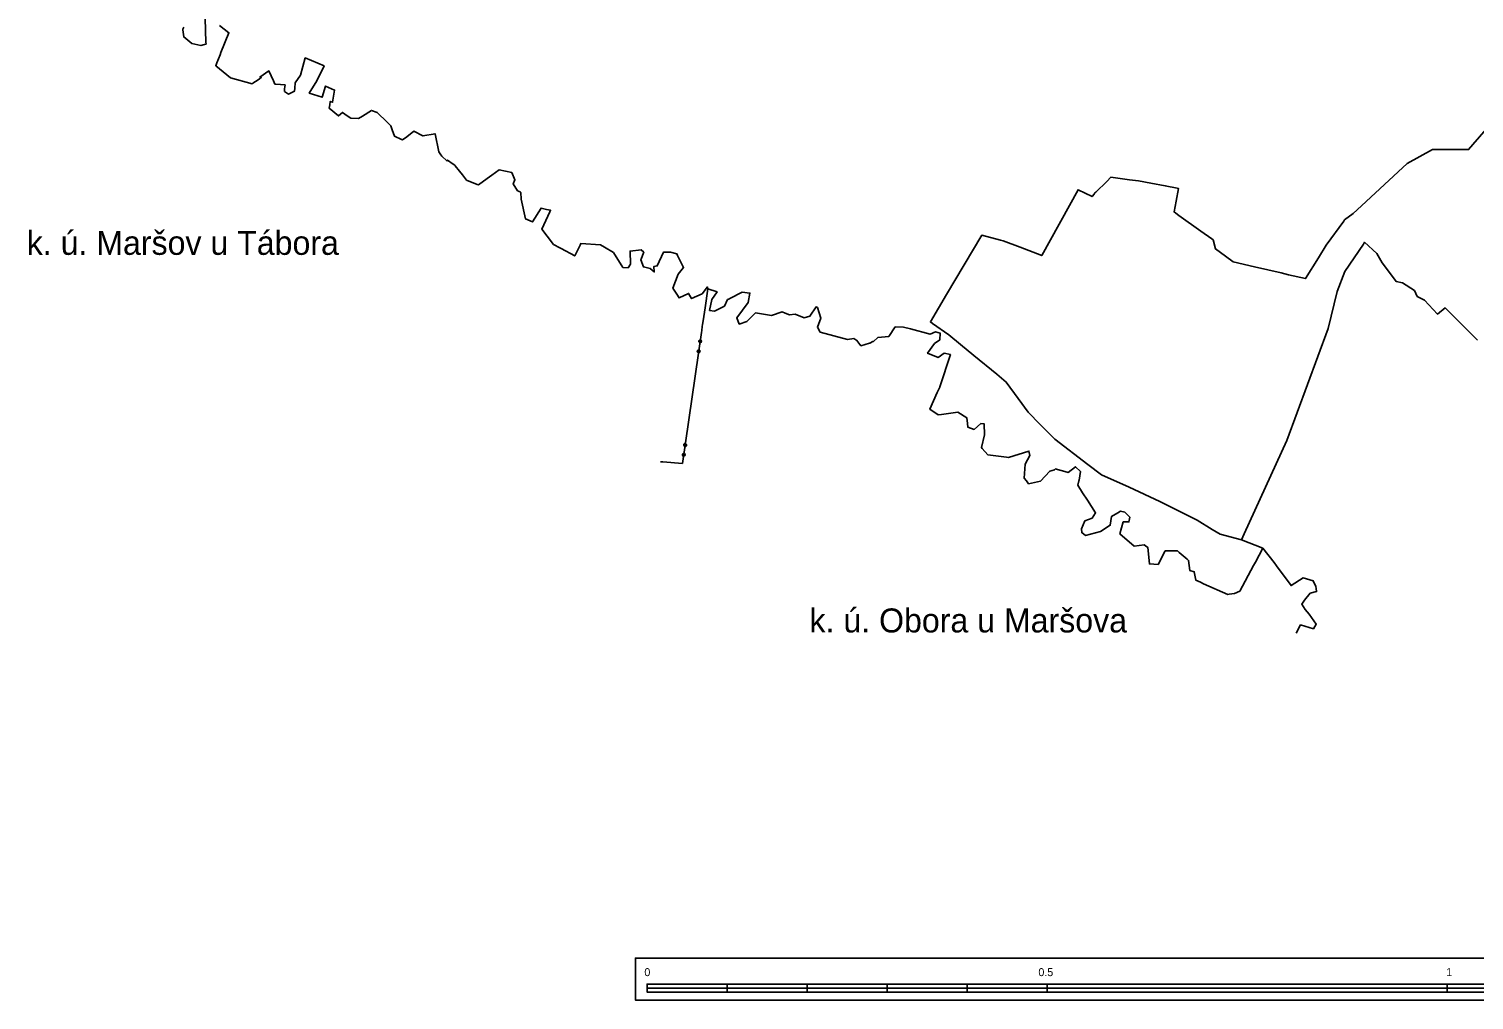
# Model space of a CAD drawing. Extents: x -738273 to -735126, y -1127782 to -1123636.
# Drawn here: x -738273 to -736466, y -1127782 to -1126567 of the extents above; entities that cross this region are included whole.
import ezdxf

# ---------------------------------------------------------------- set-up
doc = ezdxf.new("R2010")
doc.units = 0
for name, color, linetype in [('GR_MER', 7, 'Continuous'), ('HRA_KU', 7, 'Continuous'), ('KU_OST', 7, 'Continuous'), ('NERES_SET', 7, 'Continuous'), ('OVNE_PRE', 7, 'Continuous'), ('OVNE_SET', 7, 'Continuous')]:
    doc.layers.add(name, color=color, linetype=linetype)

msp = doc.modelspace()

# ---------------------------------------------------------------- linework, layer by layer
at = {"layer": 'GR_MER'}
for points in [[(-735903.2, -1127729.5), (-735903.2, -1127782), (-737514.6, -1127782), (-737514.6, -1127729.5), (-735903.2, -1127729.5)], [(-737500.1, -1127767), (-737500.1, -1127762), (-737400.1, -1127762)], [(-737300.1, -1127772), (-737400.1, -1127772), (-737400.1, -1127767)], [(-737300.1, -1127767), (-737300.1, -1127762), (-737200.1, -1127762)], [(-737100.1, -1127772), (-737200.1, -1127772), (-737200.1, -1127767)], [(-737100.1, -1127767), (-737100.1, -1127762), (-737000.1, -1127762)], [(-736500.1, -1127772), (-737000.1, -1127772), (-737000.1, -1127767)], [(-736500.1, -1127767), (-736500.1, -1127762), (-736000.1, -1127762)]]:
    msp.add_lwpolyline(points, dxfattribs=at)
for points in [[(-737400.1, -1127772), (-737500.1, -1127772), (-737500.1, -1127767), (-737400.1, -1127767)], [(-737300.1, -1127767), (-737400.1, -1127767), (-737400.1, -1127762), (-737300.1, -1127762)], [(-737200.1, -1127772), (-737300.1, -1127772), (-737300.1, -1127767), (-737200.1, -1127767)], [(-737100.1, -1127767), (-737200.1, -1127767), (-737200.1, -1127762), (-737100.1, -1127762)], [(-737000.1, -1127772), (-737100.1, -1127772), (-737100.1, -1127767), (-737000.1, -1127767)], [(-736500.1, -1127767), (-737000.1, -1127767), (-737000.1, -1127762), (-736500.1, -1127762)], [(-736000.1, -1127772), (-736500.1, -1127772), (-736500.1, -1127767), (-736000.1, -1127767)]]:
    msp.add_lwpolyline(points, close=True, dxfattribs=at)
at = {"layer": 'HRA_KU'}
for points in [[(-737424.2, -1126892.4), (-737427.6, -1126916.3), (-737429.9, -1126932.4), (-737430.6, -1126937.3), (-737431, -1126939.7), (-737431.7, -1126944.7), (-737432, -1126946.9), (-737455.8, -1127111.1)], [(-737432.2, -1126959.2), (-737433.3, -1126960), (-737434.6, -1126959.8), (-737435.4, -1126958.7), (-737435.2, -1126957.4), (-737434.1, -1126956.6), (-737432.8, -1126956.8), (-737432, -1126957.9), (-737432.2, -1126959.2), (-737432.4, -1126959.1), (-737432.2, -1126957.9), (-737432.5, -1126957.5), (-737432.8, -1126959.5), (-737433.3, -1126959.8), (-737432.9, -1126957), (-737433.3, -1126957), (-737433.7, -1126959.7), (-737434.1, -1126959.7), (-737433.7, -1126956.9), (-737434.1, -1126956.9), (-737434.5, -1126959.6), (-737434.8, -1126959.2), (-737434.5, -1126957.2), (-737435, -1126957.5), (-737435.1, -1126958.7)], [(-737434, -1126971.6), (-737435, -1126972.4), (-737436.4, -1126972.2), (-737437.2, -1126971.1), (-737437, -1126969.8), (-737435.9, -1126969), (-737434.6, -1126969.2), (-737433.8, -1126970.2), (-737434, -1126971.6), (-737434.1, -1126971.4), (-737434, -1126970.2), (-737434.3, -1126969.7), (-737434.6, -1126971.7), (-737435.1, -1126972.1), (-737434.7, -1126969.3), (-737435, -1126969.2), (-737435.4, -1126972), (-737435.8, -1126972), (-737435.4, -1126969.2), (-737435.8, -1126969.1), (-737436.2, -1126971.9), (-737436.6, -1126971.4), (-737436.3, -1126969.5), (-737436.7, -1126969.8), (-737436.9, -1126971)], [(-737450.9, -1127088.7), (-737452, -1127089.5), (-737453.3, -1127089.3), (-737454.1, -1127088.2), (-737453.9, -1127086.9), (-737452.8, -1127086.1), (-737451.5, -1127086.3), (-737450.7, -1127087.3), (-737450.9, -1127088.7), (-737451.1, -1127088.6), (-737450.9, -1127087.4), (-737451.3, -1127087), (-737451.5, -1127088.9), (-737452, -1127089.3), (-737451.6, -1127086.5), (-737452, -1127086.5), (-737452.4, -1127089.2), (-737452.8, -1127089.2), (-737452.4, -1127086.4), (-737452.8, -1127086.3), (-737453.2, -1127089.1), (-737453.5, -1127088.7), (-737453.2, -1127086.7), (-737453.7, -1127087), (-737453.9, -1127088.2)], [(-737452.7, -1127101.1), (-737453.8, -1127101.9), (-737455.1, -1127101.7), (-737455.9, -1127100.6), (-737455.7, -1127099.3), (-737454.6, -1127098.5), (-737453.3, -1127098.6), (-737452.5, -1127099.7), (-737452.7, -1127101.1), (-737452.9, -1127100.9), (-737452.7, -1127099.7), (-737453, -1127099.2), (-737453.3, -1127101.2), (-737453.8, -1127101.6), (-737453.4, -1127098.8), (-737453.8, -1127098.7), (-737454.2, -1127101.5), (-737454.6, -1127101.4), (-737454.2, -1127098.7), (-737454.6, -1127098.6), (-737455, -1127101.4), (-737455.3, -1127100.9), (-737455, -1127099), (-737455.5, -1127099.3), (-737455.6, -1127100.5)], [(-737455.8, -1127111.1), (-737480.4, -1127109), (-737483.4, -1127108.7)], [(-736730.2, -1127216.8), (-736716.4, -1127234.7), (-736713.2, -1127239.1), (-736695.1, -1127263.6), (-736680, -1127253.9), (-736667.4, -1127257.5), (-736664.1, -1127264.6), (-736663.8, -1127267.1), (-736663.2, -1127271), (-736671.2, -1127273.2), (-736678.2, -1127281.8), (-736681.8, -1127287), (-736677.5, -1127293.6), (-736672.4, -1127299.2), (-736663.7, -1127311.7), (-736667.2, -1127317.5), (-736683.2, -1127312.8), (-736688.8, -1127323)]]:
    msp.add_lwpolyline(points, dxfattribs=at)
at = {"layer": 'NERES_SET'}
for points in [[(-736440.3, -1126680.2), (-736473.1, -1126718.4), (-736481.2, -1126718.4), (-736511.7, -1126718.2), (-736518.2, -1126718.1), (-736550.1, -1126735.6), (-736612.3, -1126793.6), (-736617.4, -1126798.3), (-736628.3, -1126806.4), (-736629.2, -1126807.7), (-736651.2, -1126838), (-736660.8, -1126853.6), (-736677, -1126879.7), (-736698.3, -1126874.8), (-736707.4, -1126872.7), (-736740.8, -1126864.9), (-736767.5, -1126858.7), (-736777, -1126851.8), (-736789.5, -1126842.5), (-736792.3, -1126831.4), (-736794.2, -1126830.1), (-736807.7, -1126820.4), (-736835.2, -1126800.7), (-736839.2, -1126797.9), (-736841.3, -1126796.4), (-736838.8, -1126782.8), (-736835.9, -1126766.9), (-736837.3, -1126766.6)], [(-736837.3, -1126766.6), (-736852.3, -1126763.5), (-736870.5, -1126760.3), (-736885.9, -1126757.6), (-736897.1, -1126756), (-736920.2, -1126752.9), (-736925.4, -1126758.1), (-736939.3, -1126771.7), (-736940.2, -1126772.6), (-736941.3, -1126774.1), (-736943.7, -1126777.1), (-736961.2, -1126768.6), (-737006.7, -1126851), (-737033.7, -1126840.6), (-737054.9, -1126832.5), (-737058.2, -1126831.6), (-737081.6, -1126825.4), (-737125.6, -1126899.7), (-737145.9, -1126933.9), (-737143.3, -1126935.8), (-737122.8, -1126950.2), (-737108.2, -1126962.1), (-737091.6, -1126975.8), (-737062.9, -1126999.4), (-737051.1, -1127009.2), (-737036.2, -1127029.7), (-737023.8, -1127046.8), (-737008.5, -1127062.2), (-736990.2, -1127080.6), (-736949, -1127112.2), (-736932.1, -1127125.3), (-736897.5, -1127140.6), (-736859, -1127158.3), (-736812.5, -1127181.9), (-736793.5, -1127193.5), (-736783.9, -1127199.4), (-736757.2, -1127206.4)]]:
    msp.add_lwpolyline(points, dxfattribs=at)
at = {"layer": 'OVNE_PRE'}
for points in [[(-738078.9, -1126565.2), (-738080.3, -1126567.7), (-738080.2, -1126568.6), (-738079.2, -1126577.5), (-738068.9, -1126585.6), (-738057.7, -1126588.3), (-738053.1, -1126586.9), (-738051.3, -1126586.4), (-738051.4, -1126584), (-738052.3, -1126554.4)], [(-738034.6, -1126563.3), (-738022.7, -1126572.2), (-738032.6, -1126596.8), (-738033.8, -1126599.9), (-738037.8, -1126610), (-738039.2, -1126613.5), (-738020.7, -1126628.5), (-737993.8, -1126636.2), (-737992.6, -1126635.4), (-737986.3, -1126631.1), (-737982.2, -1126628.3), (-737983.9, -1126627.7), (-737972.7, -1126619.9), (-737966.9, -1126632.5), (-737965.1, -1126636.5), (-737964, -1126636.7), (-737952.5, -1126637.4), (-737953, -1126642.6), (-737953.1, -1126645.6), (-737948.4, -1126649.1), (-737942.5, -1126646.3), (-737940.8, -1126645.5), (-737940.4, -1126641.5), (-737939.9, -1126635.1), (-737933.1, -1126625.4), (-737927.2, -1126603.7), (-737903.7, -1126613.7), (-737912.8, -1126632.5), (-737922.3, -1126647.7), (-737906.3, -1126653), (-737902, -1126639), (-737890.7, -1126643.9), (-737893.1, -1126659.2), (-737896.1, -1126658.2), (-737896.7, -1126662.4), (-737897.3, -1126666.6), (-737885.6, -1126676.2), (-737880.9, -1126671.9), (-737875, -1126676), (-737870.5, -1126679.2), (-737860.8, -1126679.7), (-737855.8, -1126676.5), (-737844.5, -1126669.4), (-737837.5, -1126672), (-737825, -1126684.1), (-737820.4, -1126688.6), (-737818.5, -1126693.8), (-737815.8, -1126701.4), (-737806.8, -1126705.8), (-737805.7, -1126706.3), (-737800.4, -1126702.3), (-737791.5, -1126695.5), (-737780.1, -1126701.3), (-737764.9, -1126698.6), (-737760.2, -1126721), (-737757.7, -1126724.8), (-737756.7, -1126726.4), (-737750.3, -1126732.6), (-737749.4, -1126731.5), (-737742.3, -1126736.5), (-737740.3, -1126737.9), (-737739.8, -1126738.6), (-737734.5, -1126745.3), (-737730.7, -1126750.1), (-737725.6, -1126756.6), (-737712.2, -1126761.9), (-737710.9, -1126762.4), (-737700, -1126754.5), (-737694.1, -1126750.3), (-737684.9, -1126743.6), (-737669.2, -1126747.1), (-737665.1, -1126756.1), (-737667.5, -1126761.3), (-737661.8, -1126769.9), (-737658.5, -1126771.1), (-737657.9, -1126772), (-737657.3, -1126780.2), (-737652, -1126804.9), (-737643.2, -1126808.9), (-737632.6, -1126791.5), (-737630.8, -1126791.9), (-737625.8, -1126793.1), (-737620.7, -1126794.3), (-737621.5, -1126796.1), (-737631.7, -1126817.9), (-737624.9, -1126826.6), (-737616.8, -1126837), (-737608.9, -1126841.3), (-737607.2, -1126842.2), (-737590.4, -1126851.3), (-737583.8, -1126837.8), (-737582.9, -1126835.9), (-737558.1, -1126837.4), (-737553.4, -1126840.2), (-737542, -1126847.1), (-737530.3, -1126865.8), (-737523.8, -1126866.1), (-737520.6, -1126861.7), (-737521.3, -1126845.3), (-737507.4, -1126843.6), (-737504.1, -1126846.7), (-737507.8, -1126856.3), (-737504.5, -1126865.1), (-737496.3, -1126867), (-737491.1, -1126871.3), (-737491.4, -1126864.5), (-737487.4, -1126863.9), (-737479.6, -1126846.8), (-737470.6, -1126846.6), (-737462.8, -1126848.9), (-737461.8, -1126850.9), (-737454.3, -1126865.8), (-737461.1, -1126874.3), (-737467.8, -1126891.5), (-737462.9, -1126899.2), (-737460, -1126903.8), (-737448.2, -1126898.2), (-737444.3, -1126904.6), (-737431.2, -1126898.7), (-737424.5, -1126890.1), (-737424.2, -1126892.4)], [(-737424.2, -1126892.4), (-737412.5, -1126896.3), (-737419.2, -1126905.8), (-737421.9, -1126919.5), (-737415.8, -1126920.4), (-737415, -1126920), (-737403.1, -1126914), (-737399.3, -1126905.9), (-737397.1, -1126904.8), (-737396.5, -1126904.5), (-737381.3, -1126896.8), (-737371.5, -1126897.8), (-737373.6, -1126909.7), (-737388, -1126928.9), (-737384.9, -1126936.6), (-737375.5, -1126933.2), (-737364.3, -1126922.5), (-737344.6, -1126925.7), (-737331.2, -1126921.4), (-737327.5, -1126922.8), (-737321.9, -1126924.9), (-737315.1, -1126924.1), (-737303.7, -1126928.9), (-737296.4, -1126926.6), (-737288.8, -1126915.2), (-737287.2, -1126915.9), (-737283, -1126929), (-737287.1, -1126940.6), (-737283.6, -1126946.5), (-737249.5, -1126955.8), (-737241.7, -1126954.7), (-737237.7, -1126957.1), (-737236.4, -1126958.7), (-737232.7, -1126963.6), (-737222.1, -1126960.6), (-737221.7, -1126960.4), (-737217.7, -1126958.5), (-737216.9, -1126958.2), (-737211.4, -1126953.3), (-737198, -1126952), (-737189.8, -1126940.2), (-737179.7, -1126940.3), (-737170.7, -1126942.7), (-737146.3, -1126949.2), (-737139.7, -1126946.4), (-737133.6, -1126948), (-737134.3, -1126956.4), (-737140.7, -1126961), (-737149.5, -1126973), (-737136.2, -1126978.2), (-737128.8, -1126973), (-737120.9, -1126974.8), (-737134.1, -1127014.9), (-737134.2, -1127015.4), (-737135.8, -1127018.8), (-737137.3, -1127022), (-737146.6, -1127042.8), (-737136.3, -1127050.1), (-737132.2, -1127049.5), (-737111.8, -1127046.6), (-737100.4, -1127053.7), (-737099.7, -1127060.8), (-737099.2, -1127065.4), (-737091.2, -1127068.3), (-737083, -1127061), (-737078.6, -1127061.4), (-737078.3, -1127074.9), (-737082, -1127091.1), (-737081, -1127092.2), (-737074, -1127100.1), (-737050.6, -1127103.2), (-737048.2, -1127103.5), (-737022.8, -1127095.4), (-737021.5, -1127101.1), (-737027.3, -1127111.8), (-737028.5, -1127129.1), (-737025.8, -1127132.7), (-737023.1, -1127136.3), (-737008.4, -1127133), (-736996.7, -1127120.4), (-736990.6, -1127118.9), (-736989.5, -1127117.7), (-736987.1, -1127118.4), (-736978, -1127120.8), (-736973.7, -1127122), (-736964.7, -1127114.9), (-736958.3, -1127120.9), (-736960.1, -1127131.6), (-736960.4, -1127132.7), (-736961.6, -1127137.9), (-736955.6, -1127147.4), (-736949.5, -1127156.9), (-736939.4, -1127172.8), (-736943.8, -1127179.1), (-736952.8, -1127182.7), (-736957.1, -1127192.6), (-736956.8, -1127197.3), (-736952.2, -1127200.9), (-736933.2, -1127196), (-736921.1, -1127188.1), (-736919.5, -1127177.2), (-736911.6, -1127172.6), (-736908.2, -1127170.7), (-736902.8, -1127171.8), (-736896.7, -1127178.2), (-736897.4, -1127182.1), (-736897.7, -1127183.9), (-736904.8, -1127183.9), (-736909.1, -1127199), (-736891.3, -1127214.2), (-736884.9, -1127213.5), (-736878.7, -1127212.8), (-736877.1, -1127213.8), (-736874.2, -1127215.8), (-736872.2, -1127236.6), (-736861.3, -1127237.1), (-736852.4, -1127220.2), (-736845, -1127220.3), (-736837.1, -1127220.3), (-736835.1, -1127222.1), (-736825, -1127230.6), (-736823.2, -1127232.1), (-736821.8, -1127244.7), (-736816, -1127246.2), (-736814.3, -1127256.8), (-736808.3, -1127259.4), (-736804.4, -1127261.2), (-736774.2, -1127274.7), (-736772.5, -1127274.5), (-736765.6, -1127273.6), (-736759.2, -1127270.5), (-736741.9, -1127238.4), (-736739.7, -1127234.3), (-736730.2, -1127216.8)]]:
    msp.add_lwpolyline(points, dxfattribs=at)
at = {"layer": 'OVNE_SET'}
msp.add_lwpolyline([(-736730.2, -1127216.8), (-736757.2, -1127206.4), (-736753.7, -1127198.9), (-736700.4, -1127082.2), (-736648.5, -1126942.2), (-736637.4, -1126896), (-736627.8, -1126870.7), (-736604.6, -1126836.5), (-736603.1, -1126834.2), (-736588, -1126848.4), (-736581.2, -1126860), (-736577.1, -1126865.5), (-736563.9, -1126883.3), (-736555.9, -1126885.1), (-736541, -1126894.7), (-736537.4, -1126901.9), (-736528.5, -1126906.5), (-736512.2, -1126924.1), (-736502.6, -1126916.3), (-736500.9, -1126918), (-736479.7, -1126939), (-736461.9, -1126956.6)], dxfattribs=at)

# ---------------------------------------------------------------- texts
at = {"layer": 'GR_MER'}
for s, p in [('0', (-737503.4, -1127752)), ('0.5', (-737010.9, -1127752)), ('1', (-736501.2, -1127752))]:
    msp.add_text(s, height=10, dxfattribs=at).set_placement(p)
at = {"layer": 'KU_OST'}
for s, p in [('k. ú. Maršov u Tábora', (-738275.4, -1126850)), ('k. ú. Obora u Maršova', (-737297, -1127322.2))]:
    msp.add_text(s, height=30, dxfattribs=at).set_placement(p)

doc.saveas('drawing.dxf')
